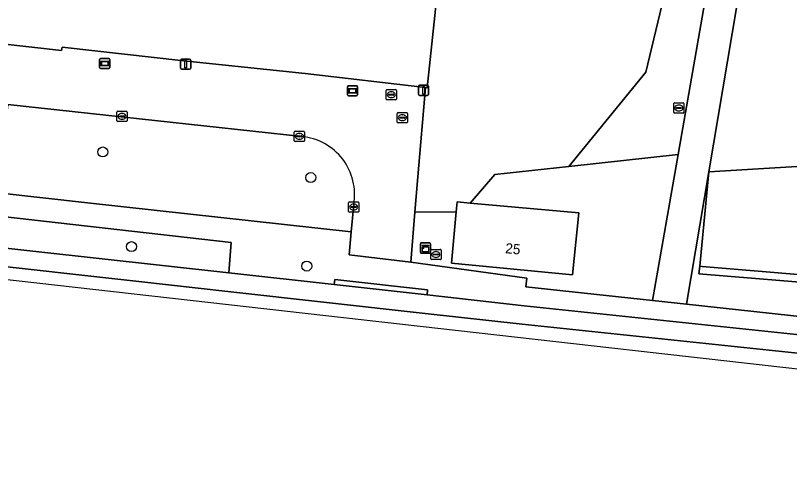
# Model space of a CAD drawing. Extents: x 162510 to 163918, y 388494 to 389774.
# Drawn here: x 163019.4 to 163095.5, y 388522.4 to 388567.4 of the extents above; entities that cross this region are included whole.
import ezdxf

# ---------------------------------------------------------------- set-up
doc = ezdxf.new("R2010")
doc.units = 0
for name, color, linetype in [('IMGEO_Berm_groen', 7, 'Continuous'), ('IMGEO_Boom', 7, 'Continuous'), ('IMGEO_Brandkraan', 7, 'Continuous'), ('IMGEO_Erf', 7, 'Continuous'), ('IMGEO_Grasland_overig', 7, 'Continuous'), ('IMGEO_Groenvoorziening', 7, 'Continuous'), ('IMGEO_Haag', 7, 'Continuous'), ('IMGEO_Kast', 7, 'Continuous'), ('IMGEO_Kolk', 7, 'Continuous'), ('IMGEO_Lichtmast', 7, 'Continuous'), ('IMGEO_Loofbos', 7, 'Continuous'), ('IMGEO_Pand', 7, 'Continuous'), ('IMGEO_Pand_nummerreeks', 7, 'Continuous'), ('IMGEO_Rijbaan_lokaal_gesloten', 7, 'Continuous'), ('IMGEO_Rijbaan_lokaal_open', 7, 'Continuous'), ('IMGEO_Rioolput', 7, 'Continuous'), ('IMGEO_Verklikker', 7, 'Continuous'), ('IMGEO_Voetpad_open', 7, 'Continuous')]:
    doc.layers.add(name, color=color, linetype=linetype)

msp = doc.modelspace()

# ---------------------------------------------------------------- linework, layer by layer
at = {"layer": 'IMGEO_Berm_groen'}
msp.add_lwpolyline([(163015.252, 388547.952), (163014.91, 388544.896), (163040.394, 388542.064), (163040.636, 388545.038)], close=True, dxfattribs=at)
at = {"layer": 'IMGEO_Boom'}
for centre in [(163028.021, 388553.953), (163048.454, 388551.441), (163030.841, 388544.65), (163048.061, 388542.734)]:
    msp.add_circle(centre, 0.489, dxfattribs=at)
at = {"layer": 'IMGEO_Brandkraan'}
for p, q in [((163055.863, 388559.157), (163055.863, 388560.009)), ((163055.938, 388560.083), (163056.79, 388560.083)), ((163056.351, 388559.863), (163056.376, 388559.863)), ((163056.864, 388560.009), (163056.864, 388559.157)), ((163056.79, 388559.083), (163055.938, 388559.083)), ((163056.122, 388559.577), (163056.122, 388559.589)), ((163056.56, 388559.54), (163056.162, 388559.54)), ((163056.165, 388559.626), (163056.563, 388559.626)), ((163056.374, 388559.303), (163056.349, 388559.303)), ((163056.606, 388559.589), (163056.606, 388559.577))]:
    msp.add_line(p, q, dxfattribs=at)
for points in [[(163055.863, 388559.157), (163055.863, 388560.009)], [(163055.938, 388560.083), (163056.79, 388560.083)], [(163056.864, 388560.009), (163056.864, 388559.157)], [(163056.79, 388559.083), (163055.938, 388559.083)]]:
    msp.add_lwpolyline(points, dxfattribs=at)
for centre, radius, start, end in [((163055.94, 388560.007), 0.0765, 91.55205, 178.44795), ((163055.94, 388560.007), 0.0765, 91.55205, 178.44795), ((163056.788, 388560.007), 0.0765, 1.55205, 88.44795), ((163056.788, 388560.007), 0.0765, 1.55205, 88.44795), ((163055.94, 388559.159), 0.0765, 181.55205, 268.44795), ((163055.94, 388559.159), 0.0765, 181.55205, 268.44795), ((163056.162, 388559.586), 0.0403, 85.87752, 175.75265), ((163056.159, 388559.576), 0.0366, 178.93798, 274.71019), ((163056.563, 388559.583), 0.043, 264.86636, 352.45326), ((163056.567, 388559.588), 0.0386, 1.73085, 96.63898), ((163056.788, 388559.159), 0.0765, 271.55205, 358.44795), ((163056.788, 388559.159), 0.0765, 271.55205, 358.44795)]:
    msp.add_arc(centre, radius, start, end, dxfattribs=at)
for centre, major_axis, ratio, start_param, end_param in [((163056.35, 388559.583), (-0.387, 0.002), 0.722429, 4.712389, 7.853982), ((163056.375, 388559.583), (-0.39, 0.002), 0.717154, 1.570796, 4.712389)]:
    msp.add_ellipse(centre, major_axis=major_axis, ratio=ratio, start_param=start_param, end_param=end_param, dxfattribs=at)
at = {"layer": 'IMGEO_Erf'}
msp.add_lwpolyline([(163012.283, 388565.224), (163023.98, 388563.913), (163024.016, 388564.261), (163035.984, 388562.926), (163047.901, 388561.655), (163059.732, 388560.275), (163059.885, 388560.257), (163061.781, 388578.223)], dxfattribs=at)
at = {"layer": 'IMGEO_Grasland_overig'}
msp.add_lwpolyline([(163157.141, 388596.515), (163157.674, 388596.664), (163157.394, 388598.247), (163156.627, 388598.047), (163151.376, 388616.641), (163152.043, 388616.813), (163152.223, 388618.507), (163150.202, 388616.103), (163145.502, 388605.218), (163139.466, 388592.856), (163124.276, 388574.27), (163108.523, 388553.238), (163096.774, 388552.545), (163087.55, 388552.001), (163086.667, 388542.733), (163086.905, 388542.71), (163117.864, 388540.098), (163165.007, 388536.066), (163165.881, 388543.752), (163165.291, 388544.507), (163165.822, 388544.867), (163165.736, 388545.383)], dxfattribs=at)
msp.add_lwpolyline([(163087.55, 388552.001), (163097.25, 388609.539), (163094.191, 388609.039), (163084.529, 388553.697), (163082.024, 388539.339), (163085.355, 388538.977)], close=True, dxfattribs=at)
at = {"layer": 'IMGEO_Groenvoorziening'}
for points in [[(163084.529, 388553.697), (163094.191, 388609.039), (163092.645, 388608.787), (163081.363, 388561.787), (163073.787, 388552.522)], [(163084.529, 388553.697), (163073.787, 388552.522), (163066.529, 388551.728), (163064.108, 388548.932), (163074.775, 388547.956), (163074.17, 388541.859), (163062.262, 388543.01), (163062.729, 388548.079), (163058.687, 388548.039), (163058.285, 388543.112), (163069.677, 388541.561), (163069.595, 388540.692), (163082.024, 388539.339)], [(163086.905, 388542.71), (163086.667, 388542.733), (163086.571, 388541.959), (163111.633, 388539.893), (163126.891, 388538.502), (163156.823, 388535.834), (163160.875, 388535.356), (163165.574, 388534.802), (163166.547, 388539.324), (163166.617, 388542.869), (163166.465, 388543.604), (163165.822, 388544.867), (163165.291, 388544.507), (163165.881, 388543.752), (163165.007, 388536.066), (163117.864, 388540.098)]]:
    msp.add_lwpolyline(points, close=True, dxfattribs=at)
for points in [[(163047.561, 388555.463), (163018.69, 388558.618), (163018.036, 388552.566), (163014.124, 388552.987), (163014.233, 388554.771), (163013.404, 388554.928), (163013.862, 388559.137), (163012.22, 388559.314)], [(163005.197, 388554.592), (163004.856, 388551.379), (163026.503, 388548.968), (163052.421, 388546.115), (163052.668, 388548.774)], [(163111.633, 388539.893), (163086.571, 388541.959), (163086.667, 388542.733), (163087.55, 388552.001), (163085.355, 388538.977), (163114.509, 388535.804)]]:
    msp.add_lwpolyline(points, dxfattribs=at)
msp.add_arc((163047.05, 388549.778), 5.708, 349.86447, 84.85844, dxfattribs=at)
at = {"layer": 'IMGEO_Haag'}
msp.add_lwpolyline([(163165.291, 388544.507), (163165.881, 388543.752), (163165.007, 388536.066), (163117.864, 388540.098), (163086.905, 388542.71), (163086.667, 388542.733), (163086.571, 388541.959), (163111.633, 388539.893), (163126.891, 388538.502), (163156.823, 388535.834), (163160.875, 388535.356), (163165.574, 388534.802), (163166.547, 388539.324), (163166.617, 388542.869), (163166.465, 388543.604), (163165.822, 388544.867)], close=True, dxfattribs=at)
at = {"layer": 'IMGEO_Kast'}
for p, q in [((163059.217, 388544.087), (163059.217, 388544.928)), ((163059.217, 388544.928), (163059.217, 388544.087)), ((163059.292, 388545.012), (163060.133, 388545.012)), ((163060.133, 388545.012), (163059.292, 388545.012)), ((163060.217, 388544.937), (163060.217, 388544.096)), ((163060.217, 388544.096), (163060.217, 388544.937)), ((163060.142, 388544.012), (163059.301, 388544.012)), ((163059.301, 388544.012), (163060.142, 388544.012))]:
    msp.add_line(p, q, dxfattribs=at)
for points in [[(163059.412, 388544.802), (163060.012, 388544.802), (163060.012, 388544.717), (163059.412, 388544.717), (163059.412, 388544.802)], [(163059.412, 388544.627), (163060.012, 388544.627), (163060.012, 388544.138), (163059.412, 388544.138), (163059.412, 388544.627)]]:
    msp.add_lwpolyline(points, dxfattribs=at)
msp.add_circle((163059.496, 388544.476), 0.0377, dxfattribs=at)
for centre, start, end in [((163059.295, 388544.934), 92.4484, 184.28452), ((163059.295, 388544.934), 92.4484, 184.28452), ((163060.139, 388544.934), 2.4484, 94.28452), ((163060.139, 388544.934), 2.4484, 94.28452), ((163059.295, 388544.09), 182.4484, 274.28452), ((163059.295, 388544.09), 182.4484, 274.28452), ((163060.139, 388544.09), 272.4484, 4.28452), ((163060.139, 388544.09), 272.4484, 4.28452)]:
    msp.add_arc(centre, 0.0779, start, end, dxfattribs=at)
at = {"layer": 'IMGEO_Kolk'}
for p, q in [((163029.411, 388557.023), (163029.411, 388557.875)), ((163029.486, 388557.949), (163030.338, 388557.949)), ((163029.899, 388557.729), (163029.924, 388557.729)), ((163030.412, 388557.875), (163030.412, 388557.023)), ((163030.338, 388556.949), (163029.486, 388556.949)), ((163029.67, 388557.443), (163029.67, 388557.455)), ((163030.108, 388557.406), (163029.71, 388557.406)), ((163029.713, 388557.492), (163030.111, 388557.492)), ((163029.922, 388557.169), (163029.897, 388557.169)), ((163030.154, 388557.455), (163030.154, 388557.443)), ((163046.908, 388555.989), (163047.76, 388555.989)), ((163046.833, 388555.063), (163046.833, 388555.915)), ((163047.092, 388555.483), (163047.092, 388555.495)), ((163047.53, 388555.446), (163047.132, 388555.446)), ((163047.135, 388555.532), (163047.533, 388555.532)), ((163047.321, 388555.769), (163047.346, 388555.769)), ((163047.576, 388555.495), (163047.576, 388555.483)), ((163047.834, 388555.915), (163047.834, 388555.063)), ((163047.76, 388554.989), (163046.908, 388554.989)), ((163047.344, 388555.209), (163047.319, 388555.209)), ((163052.168, 388548.112), (163052.168, 388548.964)), ((163052.243, 388549.038), (163053.095, 388549.038)), ((163052.427, 388548.532), (163052.427, 388548.544)), ((163052.865, 388548.495), (163052.467, 388548.495)), ((163052.47, 388548.581), (163052.868, 388548.581)), ((163052.656, 388548.818), (163052.681, 388548.818)), ((163052.911, 388548.544), (163052.911, 388548.532)), ((163053.169, 388548.964), (163053.169, 388548.112)), ((163053.095, 388548.038), (163052.243, 388548.038)), ((163052.679, 388548.258), (163052.654, 388548.258))]:
    msp.add_line(p, q, dxfattribs=at)
for points in [[(163029.411, 388557.023), (163029.411, 388557.875)], [(163029.486, 388557.949), (163030.338, 388557.949)], [(163030.412, 388557.875), (163030.412, 388557.023)], [(163030.338, 388556.949), (163029.486, 388556.949)], [(163046.908, 388555.989), (163047.76, 388555.989)], [(163046.833, 388555.063), (163046.833, 388555.915)], [(163047.834, 388555.915), (163047.834, 388555.063)], [(163047.76, 388554.989), (163046.908, 388554.989)], [(163052.168, 388548.112), (163052.168, 388548.964)], [(163052.243, 388549.038), (163053.095, 388549.038)], [(163053.169, 388548.964), (163053.169, 388548.112)], [(163053.095, 388548.038), (163052.243, 388548.038)]]:
    msp.add_lwpolyline(points, dxfattribs=at)
for centre, radius, start, end in [((163029.488, 388557.873), 0.0765, 91.55205, 178.44795), ((163029.488, 388557.873), 0.0765, 91.55205, 178.44795), ((163030.336, 388557.873), 0.0765, 1.55205, 88.44795), ((163030.336, 388557.873), 0.0765, 1.55205, 88.44795), ((163029.488, 388557.025), 0.0765, 181.55205, 268.44795), ((163029.488, 388557.025), 0.0765, 181.55205, 268.44795), ((163029.71, 388557.452), 0.0403, 85.87752, 175.75265), ((163029.707, 388557.442), 0.0366, 178.93798, 274.71019), ((163030.111, 388557.449), 0.043, 264.86636, 352.45326), ((163030.115, 388557.454), 0.0386, 1.73085, 96.63898), ((163030.336, 388557.025), 0.0765, 271.55205, 358.44795), ((163030.336, 388557.025), 0.0765, 271.55205, 358.44795), ((163046.91, 388555.913), 0.0765, 91.55205, 178.44795), ((163046.91, 388555.913), 0.0765, 91.55205, 178.44795), ((163047.758, 388555.913), 0.0765, 1.55205, 88.44795), ((163047.758, 388555.913), 0.0765, 1.55205, 88.44795), ((163047.132, 388555.492), 0.0403, 85.87752, 175.75265), ((163047.129, 388555.482), 0.0366, 178.93798, 274.71019), ((163047.533, 388555.489), 0.043, 264.86636, 352.45326), ((163047.537, 388555.494), 0.0386, 1.73085, 96.63898), ((163046.91, 388555.065), 0.0765, 181.55205, 268.44795), ((163046.91, 388555.065), 0.0765, 181.55205, 268.44795), ((163047.758, 388555.065), 0.0765, 271.55205, 358.44795), ((163047.758, 388555.065), 0.0765, 271.55205, 358.44795), ((163052.245, 388548.962), 0.0765, 91.55205, 178.44795), ((163052.245, 388548.962), 0.0765, 91.55205, 178.44795), ((163052.467, 388548.541), 0.0403, 85.87752, 175.75265), ((163052.464, 388548.531), 0.0366, 178.93798, 274.71019), ((163052.868, 388548.538), 0.043, 264.86636, 352.45326), ((163052.872, 388548.543), 0.0386, 1.73085, 96.63898), ((163053.093, 388548.962), 0.0765, 1.55205, 88.44795), ((163053.093, 388548.962), 0.0765, 1.55205, 88.44795), ((163052.245, 388548.114), 0.0765, 181.55205, 268.44795), ((163052.245, 388548.114), 0.0765, 181.55205, 268.44795), ((163053.093, 388548.114), 0.0765, 271.55205, 358.44795), ((163053.093, 388548.114), 0.0765, 271.55205, 358.44795)]:
    msp.add_arc(centre, radius, start, end, dxfattribs=at)
for centre, major_axis, ratio, start_param, end_param in [((163029.898, 388557.449), (-0.387, 0.002), 0.722429, 4.712389, 7.853982), ((163029.923, 388557.449), (-0.39, 0.002), 0.717154, 1.570796, 4.712389), ((163047.32, 388555.489), (-0.387, 0.002), 0.722429, 4.712389, 7.853982), ((163047.345, 388555.489), (-0.39, 0.002), 0.717154, 1.570796, 4.712389), ((163052.655, 388548.538), (-0.387, 0.002), 0.722429, 4.712389, 7.853982), ((163052.68, 388548.538), (-0.39, 0.002), 0.717154, 1.570796, 4.712389)]:
    msp.add_ellipse(centre, major_axis=major_axis, ratio=ratio, start_param=start_param, end_param=end_param, dxfattribs=at)
at = {"layer": 'IMGEO_Lichtmast'}
for p, q in [((163035.665, 388562.185), (163035.665, 388562.985)), ((163035.665, 388562.985), (163035.665, 388562.185)), ((163035.765, 388563.085), (163036.555, 388563.085)), ((163036.555, 388563.085), (163035.765, 388563.085)), ((163036.655, 388562.985), (163036.655, 388562.185)), ((163036.655, 388562.185), (163036.655, 388562.985)), ((163036.555, 388562.085), (163035.765, 388562.085)), ((163035.765, 388562.085), (163036.555, 388562.085)), ((163059.04, 388559.616), (163059.04, 388560.416)), ((163059.04, 388560.416), (163059.04, 388559.616)), ((163059.14, 388560.516), (163059.93, 388560.516)), ((163059.93, 388560.516), (163059.14, 388560.516)), ((163060.03, 388560.416), (163060.03, 388559.616)), ((163060.03, 388559.616), (163060.03, 388560.416)), ((163059.93, 388559.516), (163059.14, 388559.516)), ((163059.14, 388559.516), (163059.93, 388559.516))]:
    msp.add_line(p, q, dxfattribs=at)
for points in [[(163036.085, 388562.96), (163036.235, 388562.96), (163036.235, 388562.21), (163036.085, 388562.21), (163036.085, 388562.96)], [(163059.46, 388560.391), (163059.61, 388560.391), (163059.61, 388559.641), (163059.46, 388559.641), (163059.46, 388560.391)]]:
    msp.add_lwpolyline(points, dxfattribs=at)
for centre, start, end in [((163035.765, 388562.985), 90, 180), ((163035.765, 388562.985), 90, 180), ((163036.555, 388562.985), 0, 90), ((163036.555, 388562.985), 360, 90), ((163035.765, 388562.185), 180, 270), ((163035.765, 388562.185), 180, 270), ((163036.555, 388562.185), 270, 0), ((163036.555, 388562.185), 270, 0), ((163059.14, 388560.416), 90, 180), ((163059.14, 388560.416), 90, 180), ((163059.93, 388560.416), 0, 90), ((163059.93, 388560.416), 360, 90), ((163059.14, 388559.616), 180, 270), ((163059.14, 388559.616), 180, 270), ((163059.93, 388559.616), 270, 0), ((163059.93, 388559.616), 270, 0)]:
    msp.add_arc(centre, 0.1, start, end, dxfattribs=at)
at = {"layer": 'IMGEO_Loofbos'}
for points in [[(163096.774, 388552.545), (163150.202, 388616.103), (163152.223, 388618.507), (163097.25, 388609.539), (163087.55, 388552.001)], [(163079.489, 388585.494), (163068.436, 388586.573), (163067.823, 388581.642), (163062.219, 388582.257), (163062.194, 388581.971), (163061.781, 388578.223), (163059.885, 388560.257), (163059.732, 388560.275), (163058.971, 388551.511), (163058.687, 388548.039), (163062.729, 388548.079), (163062.818, 388549.05), (163064.108, 388548.932), (163066.529, 388551.728), (163073.787, 388552.522), (163081.363, 388561.787), (163092.645, 388608.787), (163076.322, 388575.541), (163075.343, 388575.845), (163075.196, 388575.901)]]:
    msp.add_lwpolyline(points, close=True, dxfattribs=at)
at = {"layer": 'IMGEO_Pand'}
msp.add_lwpolyline([(163074.775, 388547.956), (163064.108, 388548.932), (163062.818, 388549.05), (163062.729, 388548.079), (163062.262, 388543.01), (163074.17, 388541.859)], close=True, dxfattribs=at)
at = {"layer": 'IMGEO_Rijbaan_lokaal_gesloten'}
for points in [[(163178.982, 388523.125), (163178.758, 388523.432), (163178.09, 388524.156), (163177.403, 388524.656), (163176.288, 388525.112), (163175.638, 388525.237), (163131.035, 388530.402), (163114.004, 388532.296), (163069.219, 388537.019), (163059.674, 388538.08), (163040.29, 388540.234), (163031.566, 388541.204), (163014.762, 388543.071), (162987.025, 388546.161), (162964.579, 388548.669), (162948.369, 388550.483), (162948.321, 388550.488), (162908.963, 388554.88), (162908.848, 388553.848), (163175.64, 388523.673), (163178.982, 388523.125)], [(163114.206, 388534.115), (163069.421, 388538.838), (163059.876, 388539.899), (163050.754, 388540.913), (163040.394, 388542.064), (163014.91, 388544.896)], [(163014.762, 388543.071), (163031.566, 388541.204), (163040.29, 388540.234), (163059.674, 388538.08), (163069.219, 388537.019), (163114.004, 388532.296)]]:
    msp.add_lwpolyline(points, dxfattribs=at)
at = {"layer": 'IMGEO_Rijbaan_lokaal_open'}
for points in [[(163047.901, 388561.655), (163035.984, 388562.926), (163024.016, 388564.261), (163023.98, 388563.913), (163012.283, 388565.224), (163000.607, 388566.496), (162999.987, 388560.86), (162999.817, 388559.316), (162998.998, 388551.886), (162998.719, 388549.807), (163004.579, 388549.125), (163004.856, 388551.379), (163005.197, 388554.592)], [(163052.668, 388548.774), (163052.421, 388546.115), (163052.208, 388543.83), (163058.285, 388543.112), (163058.687, 388548.039), (163058.971, 388551.511), (163059.732, 388560.275), (163047.901, 388561.655)], [(163012.22, 388559.314), (163013.862, 388559.137), (163018.69, 388558.618), (163047.561, 388555.463)]]:
    msp.add_lwpolyline(points, dxfattribs=at)
msp.add_arc((163047.05, 388549.778), 5.708, 349.86447, 84.85844, dxfattribs=at)
at = {"layer": 'IMGEO_Rioolput'}
for p, q in [((163084.109, 388557.85), (163084.109, 388558.702)), ((163084.184, 388558.776), (163085.036, 388558.776)), ((163084.368, 388558.27), (163084.368, 388558.282)), ((163084.411, 388558.319), (163084.809, 388558.319)), ((163084.597, 388558.556), (163084.622, 388558.556)), ((163084.852, 388558.282), (163084.852, 388558.27)), ((163085.11, 388558.702), (163085.11, 388557.85)), ((163056.951, 388556.897), (163056.951, 388557.749)), ((163057.026, 388557.823), (163057.878, 388557.823)), ((163057.439, 388557.603), (163057.464, 388557.603)), ((163057.952, 388557.749), (163057.952, 388556.897)), ((163085.036, 388557.776), (163084.184, 388557.776)), ((163084.806, 388558.233), (163084.408, 388558.233)), ((163084.62, 388557.996), (163084.595, 388557.996)), ((163057.878, 388556.823), (163057.026, 388556.823)), ((163057.21, 388557.317), (163057.21, 388557.329)), ((163057.648, 388557.28), (163057.25, 388557.28)), ((163057.253, 388557.366), (163057.651, 388557.366)), ((163057.462, 388557.043), (163057.437, 388557.043)), ((163057.694, 388557.329), (163057.694, 388557.317)), ((163060.245, 388543.447), (163060.245, 388544.299)), ((163060.32, 388544.373), (163061.172, 388544.373)), ((163060.504, 388543.867), (163060.504, 388543.879)), ((163060.942, 388543.83), (163060.544, 388543.83)), ((163060.547, 388543.916), (163060.945, 388543.916)), ((163060.733, 388544.153), (163060.758, 388544.153)), ((163060.988, 388543.879), (163060.988, 388543.867)), ((163061.246, 388544.299), (163061.246, 388543.447)), ((163061.172, 388543.373), (163060.32, 388543.373)), ((163060.756, 388543.593), (163060.731, 388543.593))]:
    msp.add_line(p, q, dxfattribs=at)
for points in [[(163084.109, 388557.85), (163084.109, 388558.702)], [(163084.184, 388558.776), (163085.036, 388558.776)], [(163085.11, 388558.702), (163085.11, 388557.85)], [(163056.951, 388556.897), (163056.951, 388557.749)], [(163057.026, 388557.823), (163057.878, 388557.823)], [(163057.952, 388557.749), (163057.952, 388556.897)], [(163085.036, 388557.776), (163084.184, 388557.776)], [(163057.878, 388556.823), (163057.026, 388556.823)], [(163060.245, 388543.447), (163060.245, 388544.299)], [(163060.32, 388544.373), (163061.172, 388544.373)], [(163061.246, 388544.299), (163061.246, 388543.447)], [(163061.172, 388543.373), (163060.32, 388543.373)]]:
    msp.add_lwpolyline(points, dxfattribs=at)
for centre, radius, start, end in [((163084.186, 388558.7), 0.0765, 91.55205, 178.44795), ((163084.186, 388558.7), 0.0765, 91.55205, 178.44795), ((163084.408, 388558.279), 0.0403, 85.87752, 175.75265), ((163084.405, 388558.269), 0.0366, 178.93798, 274.71019), ((163084.809, 388558.276), 0.043, 264.86636, 352.45326), ((163084.813, 388558.281), 0.0386, 1.73085, 96.63898), ((163085.034, 388558.7), 0.0765, 1.55205, 88.44795), ((163085.034, 388558.7), 0.0765, 1.55205, 88.44795), ((163057.028, 388557.747), 0.0765, 91.55205, 178.44795), ((163057.028, 388557.747), 0.0765, 91.55205, 178.44795), ((163057.876, 388557.747), 0.0765, 1.55205, 88.44795), ((163057.876, 388557.747), 0.0765, 1.55205, 88.44795), ((163084.186, 388557.852), 0.0765, 181.55205, 268.44795), ((163084.186, 388557.852), 0.0765, 181.55205, 268.44795), ((163085.034, 388557.852), 0.0765, 271.55205, 358.44795), ((163085.034, 388557.852), 0.0765, 271.55205, 358.44795), ((163057.028, 388556.899), 0.0765, 181.55205, 268.44795), ((163057.028, 388556.899), 0.0765, 181.55205, 268.44795), ((163057.25, 388557.326), 0.0403, 85.87752, 175.75265), ((163057.247, 388557.316), 0.0366, 178.93798, 274.71019), ((163057.651, 388557.323), 0.043, 264.86636, 352.45326), ((163057.655, 388557.328), 0.0386, 1.73085, 96.63898), ((163057.876, 388556.899), 0.0765, 271.55205, 358.44795), ((163057.876, 388556.899), 0.0765, 271.55205, 358.44795), ((163060.322, 388544.297), 0.0765, 91.55205, 178.44795), ((163060.322, 388544.297), 0.0765, 91.55205, 178.44795), ((163060.544, 388543.876), 0.0403, 85.87752, 175.75265), ((163060.541, 388543.866), 0.0366, 178.93798, 274.71019), ((163060.945, 388543.873), 0.043, 264.86636, 352.45326), ((163060.949, 388543.878), 0.0386, 1.73085, 96.63898), ((163061.17, 388544.297), 0.0765, 1.55205, 88.44795), ((163061.17, 388544.297), 0.0765, 1.55205, 88.44795), ((163060.322, 388543.449), 0.0765, 181.55205, 268.44795), ((163060.322, 388543.449), 0.0765, 181.55205, 268.44795), ((163061.17, 388543.449), 0.0765, 271.55205, 358.44795), ((163061.17, 388543.449), 0.0765, 271.55205, 358.44795)]:
    msp.add_arc(centre, radius, start, end, dxfattribs=at)
for centre, major_axis, ratio, start_param, end_param in [((163084.596, 388558.276), (-0.387, 0.002), 0.722429, 4.712389, 7.853982), ((163084.621, 388558.276), (-0.39, 0.002), 0.717154, 1.570796, 4.712389), ((163057.438, 388557.323), (-0.387, 0.002), 0.722429, 4.712389, 7.853982), ((163057.463, 388557.323), (-0.39, 0.002), 0.717154, 1.570796, 4.712389), ((163060.732, 388543.873), (-0.387, 0.002), 0.722429, 4.712389, 7.853982), ((163060.757, 388543.873), (-0.39, 0.002), 0.717154, 1.570796, 4.712389)]:
    msp.add_ellipse(centre, major_axis=major_axis, ratio=ratio, start_param=start_param, end_param=end_param, dxfattribs=at)
at = {"layer": 'IMGEO_Verklikker'}
for p, q in [((163027.712, 388562.246), (163027.712, 388563.046)), ((163027.712, 388563.046), (163027.712, 388562.246)), ((163027.812, 388563.146), (163028.602, 388563.146)), ((163028.602, 388563.146), (163027.812, 388563.146)), ((163028.702, 388563.046), (163028.702, 388562.246)), ((163028.702, 388562.246), (163028.702, 388563.046)), ((163028.602, 388562.146), (163027.812, 388562.146)), ((163027.812, 388562.146), (163028.602, 388562.146)), ((163052.051, 388559.57), (163052.051, 388560.37)), ((163052.051, 388560.37), (163052.051, 388559.57)), ((163052.151, 388560.47), (163052.941, 388560.47)), ((163052.941, 388560.47), (163052.151, 388560.47)), ((163053.041, 388560.37), (163053.041, 388559.57)), ((163053.041, 388559.57), (163053.041, 388560.37)), ((163052.941, 388559.47), (163052.151, 388559.47)), ((163052.151, 388559.47), (163052.941, 388559.47))]:
    msp.add_line(p, q, dxfattribs=at)
for points in [[(163027.813, 388562.878), (163028.601, 388562.878), (163028.601, 388562.414), (163027.813, 388562.414), (163027.813, 388562.878)], [(163027.878, 388562.813), (163027.878, 388562.479), (163028.536, 388562.479), (163028.536, 388562.813), (163027.878, 388562.813)], [(163052.152, 388560.202), (163052.94, 388560.202), (163052.94, 388559.738), (163052.152, 388559.738), (163052.152, 388560.202)], [(163052.217, 388560.137), (163052.217, 388559.803), (163052.875, 388559.803), (163052.875, 388560.137), (163052.217, 388560.137)]]:
    msp.add_lwpolyline(points, dxfattribs=at)
for centre, start, end in [((163027.812, 388563.046), 90, 180), ((163027.812, 388563.046), 90, 180), ((163028.602, 388563.046), 0, 90), ((163028.602, 388563.046), 360, 90), ((163027.812, 388562.246), 180, 270), ((163027.812, 388562.246), 180, 270), ((163028.602, 388562.246), 270, 0), ((163028.602, 388562.246), 270, 0), ((163052.151, 388560.37), 90, 180), ((163052.151, 388560.37), 90, 180), ((163052.941, 388560.37), 0, 90), ((163052.941, 388560.37), 360, 90), ((163052.151, 388559.57), 180, 270), ((163052.151, 388559.57), 180, 270), ((163052.941, 388559.57), 270, 0), ((163052.941, 388559.57), 270, 0)]:
    msp.add_arc(centre, 0.1, start, end, dxfattribs=at)
at = {"layer": 'IMGEO_Voetpad_open'}
for points in [[(163114.509, 388535.804), (163085.355, 388538.977), (163082.024, 388539.339), (163069.595, 388540.692), (163069.677, 388541.561), (163058.285, 388543.112), (163052.208, 388543.83), (163052.421, 388546.115), (163026.503, 388548.968), (163004.856, 388551.379)], [(163015.252, 388547.952), (163040.636, 388545.038), (163040.394, 388542.064), (163050.754, 388540.913), (163050.808, 388541.407), (163059.93, 388540.394), (163059.876, 388539.899), (163069.421, 388538.838), (163114.206, 388534.115), (163174.485, 388527.411), (163175.154, 388527.297), (163175.927, 388527.098), (163176.68, 388526.831), (163177.406, 388526.497), (163178.099, 388526.1), (163178.754, 388525.643), (163179.365, 388525.129), (163179.929, 388524.562), (163180.439, 388523.948), (163180.892, 388523.29), (163181.189, 388522.764), (163181.189, 388522.764), (163183.156, 388522.441)]]:
    msp.add_lwpolyline(points, dxfattribs=at)
msp.add_lwpolyline([(163050.754, 388540.913), (163059.876, 388539.899), (163059.93, 388540.394), (163050.808, 388541.407)], close=True, dxfattribs=at)

# ---------------------------------------------------------------- texts
at = {"layer": 'IMGEO_Pand_nummerreeks'}
msp.add_text('25', height=1, rotation=354.47669, dxfattribs=at).set_placement((163067.525, 388544.009))

doc.saveas('drawing.dxf')
